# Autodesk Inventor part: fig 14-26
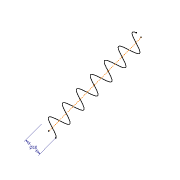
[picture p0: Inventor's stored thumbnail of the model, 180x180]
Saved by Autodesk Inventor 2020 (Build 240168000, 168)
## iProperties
Created: 2007-03
Part Number: fig 14-26
Document SubType Name: Modeling
Designer: Administrator
Density: 1 g/cm^3
Material: Generic
Appearance: Default
Author: Administrator
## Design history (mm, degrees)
node "Sketch1"
sketch "3D Sketch1"
  node "Helical Curve2" dims "d4" = 10, "d5" = 66.31, "d6" = 10, "d7" = 0
